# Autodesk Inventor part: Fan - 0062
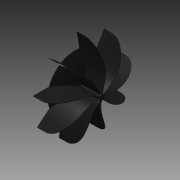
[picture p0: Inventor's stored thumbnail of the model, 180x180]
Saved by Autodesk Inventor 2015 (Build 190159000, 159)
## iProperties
Created: 2006-05
Part Number: Fan - 0062
Document SubType Name: Modeling
Designer: Autodesk, Inc.
Density: 1 g/cm^3
Description: Propeller Fan -  0062
Mass: 1278.83 g
Surface Area: 8884.25 cm^2
Volume: 1278.83 cm^3
Material: Generic
Appearance: Black Cast
Author: Autodesk, Inc.
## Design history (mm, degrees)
sketch "Sketch1"
  geometry: L1 (-343.436, 0)-(311.024, 0) reference; L2 (170, 18)-(0, 18); L3 (0, 18)-(0, 275); L4 (0, 275)-(50, 275); L5 (50, 275)-(170, 18); L6 (170, 18)-(174.823, 0); L7 (0, 18)-(170, 18); L8 (170, 18)-(170, 15); L9 (170, 15)-(0, 15); L10 (0, 15)-(0, 18); A1 r 300 centre (-249.942, 12.081) between (50, 18) and (0, 178); 2 further points
  constraints: 18 end point, 4 parallel, 4 point on line, 2 horizontal, 2 perpendicular, 2 point on circle, 1 centre point, 4 other
  dimensions: "d0" = 75 deg angle of L1 L6; "d2" = 550 diameter of L4 L1; "d3" = 50 distance of L2.end A1.start; "d4" = 50 distance of L3.end L4.end; "d5" = 160 distance from line of L3 point (160, 156.705); "d6" = 170 distance of L2.start L2.end; "d7" = 160 distance from line of L2 A1.end; "d8" = 300 radius of A1; "d9" = 3 distance between parallel lines of L2 L9; "d10" = 30 diameter of L9 L1
sketch "Sketch2"
  geometry: L1 (18, 0)-(275, 0) reference; L2 (15, 0)-(18, 0) reference; L3 (15.513, 1.41)-(14.487, -1.41); L4 (275.969, 36.421)-(274.943, 39.24); L5 (275.969, 36.421)-(516.026, 123.795); L6 (516.026, 123.795)-(515, 126.614); L7 (515, 126.614)-(274.943, 39.24); L8 (15.513, 1.41)-(12.694, 2.436); L9 (12.694, 2.436)-(11.668, -0.383); L10 (11.668, -0.383)-(14.487, -1.41); L11 (515, 126.614)-(15, 126.614); L12 (15, 126.614)-(15, 0)
  constraints: 20 end point, 5 perpendicular, 3 equal length, 2 parallel, 1 midpoint, 1 vertical, 8 other
  dimensions: "d15" = 3 distance of L4.start L4.end; "d16" = 500 distance of L6.end L11.end; "d17" = 20 deg angle of L11 L7; "d18" = 20 deg angle of L11 L8
extrude "Extrusion1" new body sketch "Sketch1" stored distance "d19" = 100; taper "d20" = 0 deg
extrude "Extrusion2" sketch "Sketch2" distance "d21" = 300; taper "d22" = 0 deg
pattern_circular "Circular Pattern1" dims "d24" = 360 deg
feature "RevolutionSrf1" dims angle "d11" = 90 deg
thicken "Thicken1" dims "d12" = 3, "d13" = 3
revolve "Revolution1" stored, may be unused: angle "d14" = 90 deg
thicken "Thicken2" dims "d26" = 3, "d27" = 3
sketch "Sketch3"
  geometry: A1 r 18 centre (0, 0) between (0, 18) and (-11.57, 13.789) reference; A2 r 18 centre (0, 0) between (-11.57, 13.789) and (-17.727, 3.126) reference; A3 r 18 centre (0, 0) between (-17.727, 3.126) and (-15.588, -9) reference; A4 r 18 centre (0, 0) between (-15.588, -9) and (-6.156, -16.914) reference; A5 r 18 centre (0, 0) between (-6.156, -16.914) and (6.156, -16.914) reference; A6 r 18 centre (0, 0) between (6.156, -16.914) and (15.588, -9) reference; A7 r 18 centre (0, 0) between (15.588, -9) and (17.727, 3.126) reference; A8 r 18 centre (0, 0) between (17.727, 3.126) and (11.57, 13.789) reference; A9 r 18 centre (0, 0) between (11.57, 13.789) and (0, 18) reference
extrude "Extrusion3" join sketch "Sketch3" distance "d28" = 2; taper "d29" = 0 deg
fillet "Fillet1" dims "d30" = 2
body "Solid1"
body "Srf1"
